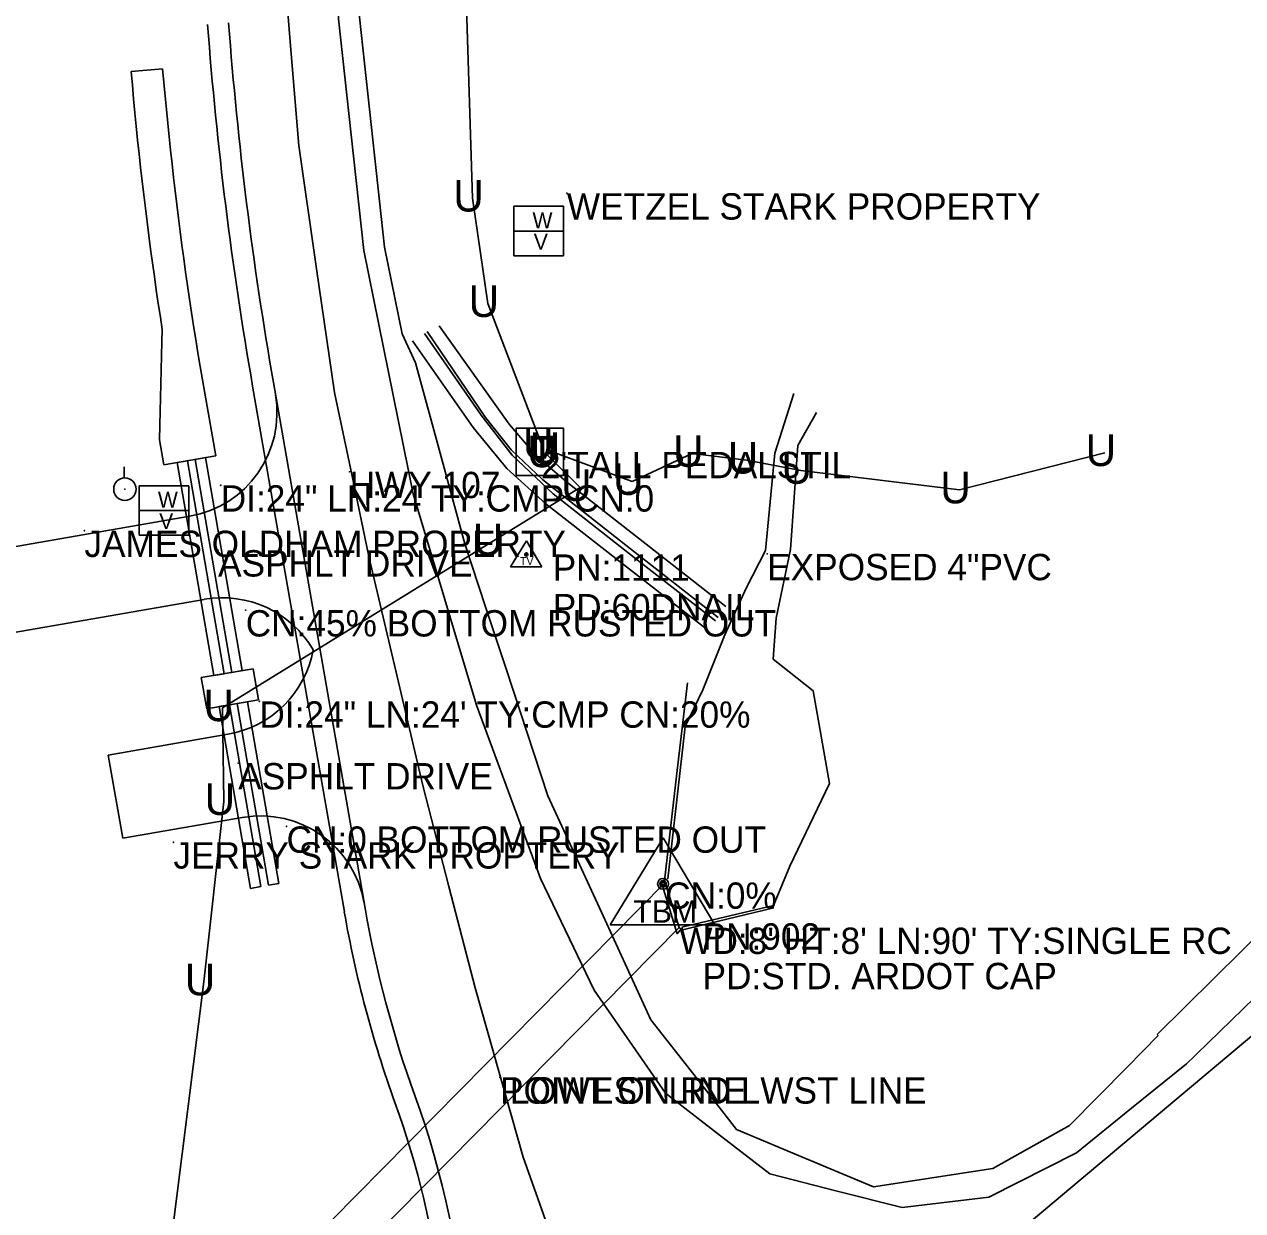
# Model space of a CAD drawing. Extents: x 1282810 to 1284464, y 402460 to 405899.
# Drawn here: x 1283626 to 1283857.3, y 404638.4 to 404863.5 of the extents above; entities that cross this region are included whole.
import ezdxf

# ---------------------------------------------------------------- set-up
doc = ezdxf.new("R2010")
doc.units = 0
for name, color, linetype in [('Default', 7, 'Continuous'), ('MOT_Drainage_Stage 2', 7, 'Continuous'), ('MOT_Driveway_Stage 2', 7, 'Continuous'), ('MOT_Proposed Road_Stage 2', 7, 'Continuous'), ('MOT_Shld_Stage 2', 7, 'Continuous'), ('MOT_Stage 1_Conc Ditch Paving', 7, 'Continuous'), ('S_BASELINE', 7, 'Continuous'), ('S_CROSS_DRAIN', 7, 'Continuous'), ('S_CROSS_DRAIN_ANNOT', 7, 'Continuous'), ('S_DITCHLINE', 7, 'Continuous'), ('S_DRG_PT_SYM', 7, 'Continuous'), ('S_EDGE_CONCRETE', 7, 'Continuous'), ('S_EDGE_PAVEMENT', 7, 'Continuous'), ('S_ELECTRIC_UTILITIES_ANNOT', 7, 'Continuous'), ('S_HEADWALL', 7, 'Continuous'), ('S_MSC_PT_SYM', 7, 'Continuous'), ('S_PAVEMENT_CROWN', 7, 'Continuous'), ('S_PRIMARY_CTL', 7, 'Continuous'), ('S_PRIMARY_CTL_ANNOT', 7, 'Continuous'), ('S_SECONDARY_CTL', 7, 'Continuous'), ('S_SECONDARY_CTL_ANNOT', 7, 'Continuous'), ('S_SHOULDER', 7, 'Continuous'), ('S_SURVEY_TEXT_ANNOT', 7, 'Continuous'), ('S_TELEPHONE_UTILITIES', 7, 'Continuous'), ('S_TELEPHONE_UTILITIES_ANNOT', 7, 'Continuous'), ('S_UNDERGROUND_CABLE', 7, 'Continuous'), ('S_UTILITY_POLE', 7, 'Continuous'), ('S_UTL_PT_SYM', 7, 'Continuous'), ('S_WATER_UTILITIES', 7, 'Continuous')]:
    doc.layers.add(name, color=color, linetype=linetype)

msp = doc.modelspace()

# ---------------------------------------------------------------- linework, layer by layer
at = {"layer": 'MOT_Drainage_Stage 2'}
for p, q in [((1283655.02, 404780.35), (1283656.99, 404780.69)), ((1283655.02, 404780.35), (1283661.98, 404739.94)), ((1283656.99, 404780.69), (1283663.95, 404740.28)), ((1283658.47, 404780.94), (1283660.44, 404781.28)), ((1283658.47, 404780.94), (1283665.43, 404740.54)), ((1283660.44, 404781.28), (1283667.4, 404740.88)), ((1283663.95, 404740.28), (1283661.98, 404739.94)), ((1283667.4, 404740.88), (1283665.43, 404740.54)), ((1283664.97, 404734.37), (1283663, 404734.03)), ((1283663, 404734.03), (1283668.95, 404699.54)), ((1283664.97, 404734.37), (1283670.92, 404699.88)), ((1283668.42, 404734.96), (1283666.45, 404734.62)), ((1283666.45, 404734.62), (1283672.4, 404700.13)), ((1283668.42, 404734.96), (1283674.37, 404700.47)), ((1283668.95, 404699.54), (1283670.92, 404699.88)), ((1283672.4, 404700.13), (1283674.37, 404700.47))]:
    msp.add_line(p, q, dxfattribs=at)
at = {"layer": 'MOT_Driveway_Stage 2'}
for p, q in [((1283613.47, 404762.48), (1283657.44, 404770.15)), ((1283616.22, 404746.72), (1283660.19, 404754.39)), ((1283641.96, 404724.82), (1283664.66, 404728.78)), ((1283641.96, 404724.82), (1283644.71, 404709.06)), ((1283644.71, 404709.06), (1283667.41, 404713.02))]:
    msp.add_line(p, q, dxfattribs=at)
for centre, start, end in [((1283654, 404789.86), 279.8958, 9.8958), ((1283663.63, 404734.69), 30.3831, 99.8958), ((1283661.22, 404748.48), 279.8958, 349.4085), ((1283670.85, 404693.31), 9.8958, 99.8958)]:
    msp.add_arc(centre, 20, start, end, dxfattribs=at)
at = {"layer": 'MOT_Proposed Road_Stage 2'}
for p, q in [((1283690.72, 404695.78), (1283673.31, 404795.54)), ((1283846.28, 404665.93), (1283859.57, 404678.85))]:
    msp.add_line(p, q, dxfattribs=at)
msp.add_lwpolyline([(1283683.36, 404909.58), (1283684.52, 404887.05), (1283685.68, 404864.53), (1283688.07, 404842.56), (1283690.46, 404820.59), (1283695.16, 404797.49), (1283699.85, 404774.39), (1283705.86, 404754.34), (1283711.86, 404734.29), (1283717.93, 404717.85), (1283724, 404701.42), (1283734.19, 404680.26), (1283747.72, 404660.7), (1283757.62, 404653.05), (1283767.51, 404645.4), (1283780.09, 404642.18), (1283792.68, 404638.97), (1283809.12, 404640.98), (1283825.72, 404649.39), (1283836.19, 404657.81), (1283846.65, 404666.23)], dxfattribs=at)
for centre, radius, start, end in [((1284368.31, 404916.78), 705.49, 184.30872, 189.89583), ((1283899.6, 404732.22), 212.04, 189.8958, 199.8404), ((1283535.54, 404600.86), 175, 318.458, 19.8404)]:
    msp.add_arc(centre, radius, start, end, dxfattribs=at)
at = {"layer": 'MOT_Shld_Stage 2'}
for p, q in [((1283686.78, 404695.1), (1283669.37, 404794.85)), ((1283841.08, 404671.79), (1283932.12, 404762.04)), ((1283841.08, 404671.79), (1283841.25, 404671.62))]:
    msp.add_line(p, q, dxfattribs=at)
for centre, radius, start, end in [((1284368.31, 404916.78), 709.49, 184.30872, 189.89583), ((1283899.6, 404732.22), 216.04, 189.8958, 199.8404), ((1283535.54, 404600.86), 171, 329.8592, 19.8404)]:
    msp.add_arc(centre, radius, start, end, dxfattribs=at)
at = {"layer": 'MOT_Stage 1_Conc Ditch Paving'}
for p, q in [((1283652.29, 404855.06), (1283646.31, 404854.53)), ((1283652.5, 404779.91), (1283662.36, 404781.61)), ((1283669.47, 404741.23), (1283659.61, 404739.53)), ((1283670.51, 404735.32), (1283669.47, 404741.23)), ((1283660.65, 404733.62), (1283659.61, 404739.53)), ((1283670.51, 404735.32), (1283660.65, 404733.62))]:
    msp.add_line(p, q, dxfattribs=at)
for points in [[(1283646.31, 404854.53), (1283646.54, 404851.94), (1283646.78, 404849.34), (1283647.02, 404846.74), (1283647.28, 404844.15), (1283647.55, 404841.55), (1283647.82, 404838.96), (1283648.11, 404836.36), (1283648.4, 404833.77), (1283648.71, 404831.18), (1283649.02, 404828.59), (1283649.34, 404826), (1283649.67, 404823.41), (1283650.01, 404820.83), (1283650.36, 404818.24), (1283650.72, 404815.66), (1283651.09, 404813.08), (1283651.47, 404810.5), (1283651.86, 404807.92), (1283652.21, 404805.62), (1283652.13, 404803.25), (1283652.05, 404800.59), (1283651.98, 404797.93), (1283651.92, 404795.27), (1283651.87, 404792.62), (1283651.81, 404790.07), (1283651.67, 404784.68), (1283652.5, 404779.91)], [(1283662.36, 404781.61), (1283660.29, 404793.49), (1283659.85, 404796.05), (1283659.42, 404798.6), (1283659, 404801.15), (1283658.58, 404803.7), (1283658.18, 404806.26), (1283657.79, 404808.82), (1283657.4, 404811.38), (1283657.03, 404813.94), (1283656.66, 404816.5), (1283656.31, 404819.06), (1283655.96, 404821.62), (1283655.62, 404824.19), (1283655.29, 404826.75), (1283654.97, 404829.32), (1283654.66, 404831.89), (1283654.36, 404834.46), (1283654.07, 404837.03), (1283653.79, 404839.6), (1283653.52, 404842.17), (1283653.25, 404844.75), (1283653, 404847.32), (1283652.75, 404849.9), (1283652.52, 404852.47), (1283652.29, 404855.06)]]:
    msp.add_lwpolyline(points, dxfattribs=at)
at = {"layer": 'S_BASELINE'}
msp.add_line((1283700.58, 404538.68), (1284334.82, 405070.64), dxfattribs=at)
at = {"layer": 'S_CROSS_DRAIN'}
for p, q in [((1283684.33, 404636.51), (1283747.67, 404700.67)), ((1283747.67, 404700.67), (1283750.34, 404692.1)), ((1283750.34, 404692.1), (1283686.84, 404627.88))]:
    msp.add_line(p, q, dxfattribs=at)
at = {"layer": 'S_DITCHLINE'}
for points in [[(1283702.51, 404805.24), (1283713.56, 404788.88), (1283718.45, 404782.78), (1283724.48, 404777.04), (1283741.09, 404763.99), (1283757.7, 404750.94)], [(1283757.22, 404750.29), (1283741.81, 404762.35), (1283726.39, 404774.41), (1283718.6, 404781.73), (1283712.72, 404789.35), (1283701.97, 404804.81)], [(1283748.19, 404701.34), (1283749.83, 404715.79), (1283751.48, 404730.24), (1283754.85, 404737.22), (1283759.01, 404747.63), (1283763.03, 404756.5), (1283766.69, 404763.65), (1283768.49, 404782.13), (1283772.12, 404793.44)], [(1283776.42, 404789.84), (1283772.85, 404783.6), (1283771.44, 404763.88), (1283768.73, 404750.83), (1283768.19, 404743.03), (1283775.75, 404737.06), (1283778.86, 404719.43), (1283771.33, 404703.75), (1283768.22, 404696.27), (1283750.82, 404692.2)]]:
    msp.add_lwpolyline(points, dxfattribs=at)
at = {"layer": 'S_DRG_PT_SYM'}
for points in [[(1283663.32, 404776.04), (1283663.32, 404776.09), (1283663.32, 404776.04), (1283663.27, 404776.04), (1283663.32, 404776.04), (1283663.32, 404775.99), (1283663.32, 404776.04), (1283663.37, 404776.04)], [(1283668.06, 404752.34), (1283668.06, 404752.39), (1283668.06, 404752.34), (1283668.01, 404752.34), (1283668.06, 404752.34), (1283668.06, 404752.29), (1283668.06, 404752.34), (1283668.11, 404752.34)], [(1283670.66, 404735.03), (1283670.66, 404735.08), (1283670.66, 404735.03), (1283670.61, 404735.03), (1283670.66, 404735.03), (1283670.66, 404734.98), (1283670.66, 404735.03), (1283670.71, 404735.03)], [(1283675.81, 404711.3), (1283675.81, 404711.35), (1283675.81, 404711.3), (1283675.76, 404711.3), (1283675.81, 404711.3), (1283675.81, 404711.25), (1283675.81, 404711.3), (1283675.86, 404711.3)], [(1283747.67, 404700.67), (1283747.67, 404700.72), (1283747.67, 404700.67), (1283747.62, 404700.67), (1283747.67, 404700.67), (1283747.67, 404700.62), (1283747.67, 404700.67), (1283747.72, 404700.67)], [(1283750.34, 404692.1), (1283750.34, 404692.15), (1283750.34, 404692.1), (1283750.29, 404692.1), (1283750.34, 404692.1), (1283750.34, 404692.05), (1283750.34, 404692.1), (1283750.39, 404692.1)]]:
    msp.add_lwpolyline(points, dxfattribs=at)
at = {"layer": 'S_EDGE_CONCRETE'}
for points in [[(1283759.18, 404753.04), (1283744.06, 404764.86), (1283728.95, 404776.68), (1283723.16, 404781.6), (1283718.04, 404787.6), (1283704.78, 404806.31)], [(1283699.7, 404803.45), (1283711.22, 404786.97), (1283717.61, 404779.19), (1283725, 404772.54), (1283740.36, 404760.58), (1283755.72, 404748.62)]]:
    msp.add_lwpolyline(points, dxfattribs=at)
at = {"layer": 'S_EDGE_PAVEMENT'}
msp.add_lwpolyline([(1283683.36, 404909.58), (1283684.52, 404887.05), (1283685.68, 404864.53), (1283688.07, 404842.56), (1283690.46, 404820.59), (1283695.16, 404797.49), (1283699.85, 404774.39), (1283705.86, 404754.34), (1283711.86, 404734.29), (1283717.93, 404717.85), (1283724, 404701.42), (1283734.19, 404680.26), (1283747.72, 404660.7), (1283757.62, 404653.05), (1283767.51, 404645.4), (1283780.09, 404642.18), (1283792.68, 404638.97), (1283809.12, 404640.98), (1283825.72, 404649.39), (1283836.19, 404657.81), (1283846.65, 404666.23)], dxfattribs=at)
at = {"layer": 'S_HEADWALL'}
msp.add_lwpolyline([(1283751.91, 404738.52), (1283749.72, 404719.76), (1283747.53, 404701), (1283746.93, 404700.88), (1283749.93, 404690.94), (1283750.44, 404691.52), (1283768.27, 404695.87)], dxfattribs=at)
at = {"layer": 'S_MSC_PT_SYM'}
for points in [[(1283729.01, 404831.45), (1283729.01, 404831.5), (1283729.01, 404831.45), (1283728.96, 404831.45), (1283729.01, 404831.45), (1283729.01, 404831.4), (1283729.01, 404831.45), (1283729.06, 404831.45)], [(1283687.78, 404778.59), (1283687.78, 404778.64), (1283687.78, 404778.59), (1283687.73, 404778.59), (1283687.78, 404778.59), (1283687.78, 404778.54), (1283687.78, 404778.59), (1283687.83, 404778.59)], [(1283637.45, 404767.42), (1283637.45, 404767.47), (1283637.45, 404767.42), (1283637.4, 404767.42), (1283637.45, 404767.42), (1283637.45, 404767.37), (1283637.45, 404767.42), (1283637.5, 404767.42)], [(1283662.81, 404763.72), (1283662.81, 404763.77), (1283662.81, 404763.72), (1283662.76, 404763.72), (1283662.81, 404763.72), (1283662.81, 404763.67), (1283662.81, 404763.72), (1283662.86, 404763.72)], [(1283767.04, 404763.02), (1283767.04, 404763.07), (1283767.04, 404763.02), (1283766.99, 404763.02), (1283767.04, 404763.02), (1283767.04, 404762.97), (1283767.04, 404763.02), (1283767.09, 404763.02)], [(1283666.64, 404723.32), (1283666.64, 404723.36), (1283666.64, 404723.32), (1283666.59, 404723.32), (1283666.64, 404723.32), (1283666.64, 404723.27), (1283666.64, 404723.32), (1283666.69, 404723.32)], [(1283654.34, 404708.3), (1283654.34, 404708.35), (1283654.34, 404708.3), (1283654.29, 404708.3), (1283654.34, 404708.3), (1283654.34, 404708.25), (1283654.34, 404708.3), (1283654.39, 404708.3)], [(1283716.32, 404663.7), (1283716.32, 404663.75), (1283716.32, 404663.7), (1283716.27, 404663.7), (1283716.32, 404663.7), (1283716.32, 404663.65), (1283716.32, 404663.7), (1283716.37, 404663.7)]]:
    msp.add_lwpolyline(points, dxfattribs=at)
at = {"layer": 'S_PAVEMENT_CROWN'}
msp.add_lwpolyline([(1283763.06, 404581.02), (1283757.18, 404587.96), (1283744.84, 404602.59), (1283735.46, 404615.11), (1283727.38, 404629.8), (1283720.71, 404648.55), (1283716.16, 404664.6), (1283711.6, 404680.66), (1283706.63, 404699.87), (1283701.66, 404719.08), (1283696.55, 404740.81), (1283691.44, 404762.55), (1283688.17, 404778.09), (1283684.91, 404793.63), (1283681.52, 404817.08), (1283678.14, 404840.54), (1283676.65, 404858.67), (1283675.16, 404876.81), (1283674.46, 404891.63), (1283673.76, 404906.45)], dxfattribs=at)
at = {"layer": 'S_PRIMARY_CTL'}
for p, q in [((1283747.27, 404709.11), (1283737.24, 404692.6)), ((1283747.27, 404709.11), (1283757.09, 404692.6)), ((1283737.24, 404692.6), (1283757.09, 404692.6))]:
    msp.add_line(p, q, dxfattribs=at)
for radius in [1.04, 0.609, 0.344]:
    msp.add_circle((1283747.27, 404700.41), radius, dxfattribs=at)
at = {"layer": 'S_SECONDARY_CTL'}
for p, q in [((1283721.32, 404765.52), (1283718.31, 404760.57)), ((1283721.32, 404765.52), (1283724.27, 404760.57)), ((1283718.31, 404760.57), (1283724.27, 404760.57))]:
    msp.add_line(p, q, dxfattribs=at)
for radius in [0.311, 0.183, 0.103]:
    msp.add_circle((1283721.32, 404762.91), radius, dxfattribs=at)
at = {"layer": 'S_SHOULDER'}
for points in [[(1283687.35, 404909.78), (1283689.67, 404864.85), (1283694.42, 404821.2), (1283697.76, 404804.78)], [(1283841.25, 404671.62), (1283835.33, 404665.61), (1283824.41, 404654.54), (1283809.86, 404646.39), (1283787.19, 404642.89), (1283774.2, 404648.35), (1283761.21, 404653.8), (1283753.08, 404664.2), (1283744.96, 404674.6), (1283735.18, 404695.84), (1283725.41, 404717.08), (1283721.47, 404729.04), (1283717.53, 404741), (1283713.6, 404752.95), (1283709.66, 404764.91), (1283704.99, 404782.1), (1283700.31, 404799.29), (1283697.76, 404804.78)]]:
    msp.add_lwpolyline(points, dxfattribs=at)
at = {"layer": 'S_TELEPHONE_UTILITIES'}
msp.add_lwpolyline([(1283719.37, 404777.86), (1283719.37, 404786.86), (1283728.37, 404786.86), (1283728.37, 404777.86)], close=True, dxfattribs=at)
at = {"layer": 'S_UNDERGROUND_CABLE'}
for p, q in [((1283711.08, 404830.54), (1283709.4, 404885.24)), ((1283713.99, 404810.51), (1283711.08, 404830.54)), ((1283724.31, 404783.55), (1283713.99, 404810.51)), ((1283731.56, 404775.59), (1283725.07, 404782.01)), ((1283741.42, 404776.76), (1283725.6, 404782.66)), ((1283752.79, 404782.08), (1283741.42, 404776.76)), ((1283763.16, 404780.81), (1283752.79, 404782.08)), ((1283831.1, 404782.22), (1283803.51, 404775.16)), ((1283773.39, 404778.87), (1283763.16, 404780.81)), ((1283803.51, 404775.16), (1283773.39, 404778.87)), ((1283714.79, 404765.29), (1283731.56, 404775.59)), ((1283663.67, 404733.83), (1283714.79, 404765.29)), ((1283663.88, 404716.02), (1283663.67, 404733.83)), ((1283660.12, 404681.79), (1283663.88, 404716.02)), ((1283649.11, 404594.2), (1283660.12, 404681.79))]:
    msp.add_line(p, q, dxfattribs=at)
at = {"layer": 'S_UTILITY_POLE'}
msp.add_line((1283645.01, 404777.43), (1283645.01, 404779.54), dxfattribs=at)
msp.add_circle((1283645.13, 404775.29), 2.13, dxfattribs=at)
at = {"layer": 'S_UTL_PT_SYM'}
for points in [[(1283645.13, 404775.29), (1283645.13, 404775.34), (1283645.13, 404775.29), (1283645.08, 404775.29), (1283645.13, 404775.29), (1283645.13, 404775.24), (1283645.13, 404775.29), (1283645.18, 404775.29)], [(1283716.32, 404663.7), (1283716.32, 404663.75), (1283716.32, 404663.7), (1283716.27, 404663.7), (1283716.32, 404663.7), (1283716.32, 404663.65), (1283716.32, 404663.7), (1283716.37, 404663.7)]]:
    msp.add_lwpolyline(points, dxfattribs=at)
at = {"layer": 'S_WATER_UTILITIES'}
for p, q in [((1283718.94, 404828.97), (1283728.36, 404828.97)), ((1283718.94, 404819.56), (1283718.94, 404828.97)), ((1283728.36, 404828.97), (1283728.36, 404819.56)), ((1283718.94, 404824.28), (1283728.36, 404824.28)), ((1283728.36, 404819.56), (1283718.94, 404819.56)), ((1283647.84, 404775.95), (1283657.26, 404775.95)), ((1283647.84, 404766.54), (1283647.84, 404775.95)), ((1283657.26, 404775.95), (1283657.26, 404766.54)), ((1283647.84, 404771.27), (1283657.26, 404771.27)), ((1283657.26, 404766.54), (1283647.84, 404766.54))]:
    msp.add_line(p, q, dxfattribs=at)

# ---------------------------------------------------------------- texts
at = {"layer": 'Default'}
for p in [(1283707.45, 404827.99), (1283710.36, 404807.97), (1283720.68, 404781), (1283721.44, 404779.46), (1283721.97, 404780.11), (1283749.16, 404779.53), (1283759.53, 404778.26), (1283827.47, 404779.68), (1283769.76, 404776.32), (1283737.79, 404774.22), (1283727.93, 404773.04), (1283799.88, 404772.61), (1283711.16, 404762.75), (1283660.04, 404731.28), (1283660.25, 404713.48), (1283656.49, 404679.25)]:
    msp.add_text('U', height=6, rotation=360, dxfattribs=at).set_placement(p)
at = {"layer": 'S_CROSS_DRAIN_ANNOT'}
for s, p in [('DI:24" LN:24 TY:CMP CN:0', (1283663.32, 404771.04)), ('CN:45% BOTTOM RUSTED OUT', (1283668.06, 404747.34)), ('DI:24" LN:24\' TY:CMP CN:20%', (1283670.66, 404730.03)), ('CN:0 BOTTOM RUSTED OUT', (1283675.81, 404706.3)), ('CN:0%', (1283747.67, 404695.67)), ("WD:8' HT:8' LN:90' TY:SINGLE RC", (1283750.34, 404687.1))]:
    msp.add_text(s, height=5, dxfattribs=at).set_placement(p)
at = {"layer": 'S_ELECTRIC_UTILITIES_ANNOT'}
msp.add_text(' LOWEST LINE', height=5, dxfattribs=at).set_placement((1283716.32, 404658.7))
at = {"layer": 'S_PRIMARY_CTL'}
msp.add_text('TBM', height=4.287, rotation=360, dxfattribs=at).set_placement((1283741.62, 404693.02))
at = {"layer": 'S_PRIMARY_CTL_ANNOT'}
for s, p in [('PN:902', (1283754.77, 404687.91)), ('PD:STD. ARDOT CAP', (1283754.77, 404680.41))]:
    msp.add_text(s, height=5, dxfattribs=at).set_placement(p)
at = {"layer": 'S_SECONDARY_CTL'}
msp.add_text('TV', height=1.5, rotation=360, dxfattribs=at).set_placement((1283720.12, 404760.9))
at = {"layer": 'S_SECONDARY_CTL_ANNOT'}
for s, p in [('PN:1111', (1283726.32, 404757.91)), ('PD:60DNAIL', (1283726.32, 404750.41))]:
    msp.add_text(s, height=5, dxfattribs=at).set_placement(p)
at = {"layer": 'S_SURVEY_TEXT_ANNOT'}
for s, p in [('WETZEL STARK PROPERTY ', (1283729.01, 404826.45)), ('HWY 107', (1283687.78, 404773.59)), ('JAMES OLDHAM PROPERTY', (1283637.45, 404762.42)), ('ASPHLT DRIVE', (1283662.81, 404758.72)), ('EXPOSED 4"PVC', (1283767.04, 404758.02)), ('ASPHLT DRIVE', (1283666.64, 404718.32)), ('JERRY STARK PROPTERY', (1283654.34, 404703.3)), ('POINT ON RD LWST LINE', (1283716.32, 404658.7))]:
    msp.add_text(s, height=5, dxfattribs=at).set_placement(p)
at = {"layer": 'S_TELEPHONE_UTILITIES'}
msp.add_text('T', height=6, rotation=360, dxfattribs=at).set_placement((1283721.93, 404779.36))
at = {"layer": 'S_TELEPHONE_UTILITIES_ANNOT'}
msp.add_text("2'TALL PEDALSTIL", height=5, dxfattribs=at).set_placement((1283724.1, 404777.38))
at = {"layer": 'S_WATER_UTILITIES'}
for s, p in [('W', (1283722.49, 404824.81)), ('V', (1283722.73, 404820.75)), ('W', (1283651.39, 404771.8)), ('V', (1283651.63, 404767.73))]:
    msp.add_text(s, height=3, rotation=360, dxfattribs=at).set_placement(p)

doc.saveas('drawing.dxf')
